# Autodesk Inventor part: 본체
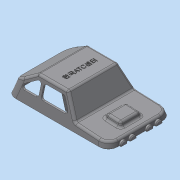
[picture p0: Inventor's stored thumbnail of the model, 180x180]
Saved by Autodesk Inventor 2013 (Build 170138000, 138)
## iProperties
Created: 2015-05
Part Number: 본체
Material: 일반
Document SubType Name: Modeling
Designer: Administrator
Density: 1 g/cm^3
Author: Administrator
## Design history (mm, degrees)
sketch "스케치1"
  geometry: L1 (-61, 38)-(61, 38); L2 (61, 38)-(61, -38); L3 (61, -38)-(-61, -38); L4 (-61, -38)-(-61, 38); L5 (-61, 38)-(61, -38); L6 (61, 38)-(-61, -38); 1 further point
  constraints: 12 end point, 2 midpoint, 2 parallel, 1 horizontal, 1 perpendicular
  dimensions: "d0" = 122 distance of L2.end L3.end; "d2" = 76 distance of L1.end L2.end
extrude "돌출1" new body sketch "스케치1" distance "d3" = 31; taper "d4" = 0 deg
sketch "스케치2"
  geometry: L1 (0, 76)-(0, 0) reference; L2 (0, 76)-(-31, 76) reference; L3 (-31, 0)-(-31, 76) reference; L4 (0, 0)-(-31, 0) reference; L5 (0, 0)-(-31, 8.306); L6 (0, 76)-(-31, 67.694); 1 further point
  constraints: 4 end point, 2 point on line
  dimensions: "d6" = 105 deg angle of L1 L5; "d7" = 105 deg angle of L1 L6
extrude "돌출2" cut sketch "스케치2" stored distance "d8" = 31; taper "d9" = 0 deg
sketch "스케치3"
  geometry: L1 (61, 31)-(-61, 31) reference; L2 (61, 0)-(61, 31) reference; L3 (31, 31)-(57.412, 13.392); L4 (31, 31)-(61, 31); L5 (61, 31)-(61, 11); L6 (61, 0)-(57.412, 13.392); L7 (61, 11)-(61, 0); L8 (57.412, 13.392)-(61, 11); 1 further point
  constraints: 12 end point, 1 collinear, 1 perpendicular, 1 vertical
  dimensions: "d10" = 20 distance of L1.start L5.end; "d12" = 30 distance of L1.start L3.start; "d13" = 15 deg angle of L2 L6; "d14" = 33.6901 deg angle of L1 L3
extrude "돌출3" cut sketch "스케치3" stored distance "d15" = 31; taper "d16" = 0 deg
sketch "스케치4"
  geometry: L1 (-61, 0)-(-59.392, 6); L2 (-61, 0)-(61, 0) reference; L3 (57.412, 13.392)-(61, 0) reference; L4 (61, 0)-(-61, 0) reference; L5 (-61, 0)-(-61, 31) reference; L6 (-61, 31)-(31, 31) reference; L7 (31, 31)-(57.412, 13.392) reference; L8 (-59.392, 6)-(-19, 8.117); L9 (-19, 8.117)-(-4.701, 31); 1 further point
  constraints: 6 end point, 1 point on line
  dimensions: "d17" = 105 deg angle of L2 L1; "d18" = 3 deg angle of L2 L8; "d19" = 6 vertical distance of L1.end L1.start; "d20" = 125 deg angle of L9 L8; "d21" = 42 horizontal distance of L8.end L1.start
extrude "돌출4" cut sketch "스케치4" stored distance "d22" = 31; taper "d23" = 0 deg
sketch "스케치5"
  geometry: L1 (-29.08, 23.392)-(-9.08, 23.392); L2 (-9.08, 23.392)-(-9.08, 49.392); L3 (-9.08, 49.392)-(-29.08, 49.392); L4 (-29.08, 49.392)-(-29.08, 23.392); L5 (-29.08, 23.392)-(-9.08, 49.392); L6 (-9.08, 23.392)-(-29.08, 49.392); L7 (1.92, 74.392)-(1.92, -1.608) reference; 3 further points
  constraints: 12 end point, 3 midpoint, 2 parallel, 1 horizontal, 1 horizontal alignment, 1 perpendicular
  dimensions: "d24" = 26 distance of L1.end L2.end; "d26" = 20 distance of L2.end L3.end; "d27" = 11 distance between parallel lines of L7 L2
extrude "돌출5" join sketch "스케치5" distance "d28" = 5; taper "d29" = -20 deg
fillet "모깎기1" dims "d30" = 12
fillet "모깎기2" dims "d31" = 3
fillet "모깎기3" dims "d32" = 3
feature "쉘1" dims "d33" = 2
sketch "스케치6"
  geometry: L1 (49.27, -35.929)-(-49.27, -35.929) reference; L2 (-58.929, -26.27)-(-58.929, 26.27) reference; L3 (-49.27, 35.929)-(49.27, 35.929) reference; L4 (58.929, 26.27)-(58.929, -26.27) reference; L5 (-59.929, 26.27)-(-59.929, -26.27); L6 (-49.27, -36.929)-(49.27, -36.929); L7 (59.929, -26.27)-(59.929, 26.27); L8 (49.27, 36.929)-(-49.27, 36.929); 5 further points; 4 other entities
  constraints: 8 end point, 7 parallel, 16 other
  dimensions: "d34" = 1 distance between parallel lines of L2 L5
extrude "돌출6" join sketch "스케치6" distance "d35" = 1; taper "d36" = 0 deg
node "작업 평면1"
sketch "스케치7"
  geometry: A1 r 4 centre (-21, 0) between (-17, 0) and (-25, 0); A2 r 4 centre (-10, 0) between (-6, 0) and (-14, 0); A3 r 4 centre (10, 0) between (14, 0) and (6, 0); A4 r 4 centre (21, 0) between (25, 0) and (17, 0); 3 further points
  constraints: 8 point on circle, 4 centre point, 4 horizontal alignment, 9 other
  dimensions: "d38" = 8 diameter of A1; "d39" = 8 diameter of A2; "d40" = 8 diameter of A3; "d41" = 8 diameter of A4; "d42" = 10 distance of point (0, 0) A2.centre; "d43" = 10 distance of A3.centre point (0, 0); "d44" = 11 distance of A4.centre A3.centre; "d45" = 11 distance of A2.centre A1.centre
extrude "돌출7" join sketch "스케치7" stored distance "d46" = 1; taper "d47" = 0 deg
chamfer "모따기1" distance "d48" = 1; stored, may be unused: second distance "d49" = 2, angle "d50" = 45 deg
sketch "스케치8"
  geometry: L1 (-61, -26.409)-(-61, 26.409) reference; 2 further points
  constraints: 1 horizontal alignment, 1 other
  dimensions: "d51" = 50 distance from line of point (-11, 0) L1
feature "엠보싱1" sketch "스케치8" dims "d0" = 122, "d2" = 76, "d52" = 0.5, "d53" = 0
sketch "스케치9"
  geometry: L1 (-3.038, 31)-(13.023, 31) reference; L2 (13.023, 31)-(13.023, 31.5) reference; L3 (13.023, 31.5)-(13.387, 31.5) reference; L4 (13.387, 31.5)-(13.387, 31) reference; L5 (13.387, 31)-(30.092, 31) reference; L6 (31.756, 30.496)-(56.471, 14.02) reference; L7 (57.704, 12.3)-(61, 0) reference; L8 (61, 0)-(59.929, 0) reference; L9 (59.929, 0)-(59.929, -1) reference; L10 (59.929, -1)-(58.929, -1) reference; L11 (58.929, -1)-(58.929, 0) reference; L12 (58.929, 0)-(55.772, 11.782) reference; L13 (55.361, 12.356)-(30.646, 28.832) reference; L14 (30.092, 29)-(-3.038, 29) reference; L15 (-3.886, 28.53)-(-16.476, 8.381) reference; L16 (-20.455, 6.038)-(-28.149, 5.635) reference; L17 (-33.013, 8.674)-(-33.451, 9.705) reference; L18 (-34.424, 10.313)-(-46.566, 9.676) reference; L19 (-47.47, 8.97)-(-47.797, 7.899) reference; L20 (-52.317, 4.368)-(-57.111, 4.117) reference; L21 (-58.025, 3.377)-(-58.929, 0) reference; L22 (-58.929, 0)-(-58.929, -1) reference; L23 (-58.929, -1)-(-59.929, -1) reference; L24 (-59.929, -1)-(-59.929, 0) reference; L25 (-59.929, 0)-(-61, 0) reference; L26 (-61, 0)-(-59.956, 3.895) reference; L27 (-57.216, 6.114)-(-52.422, 6.365) reference; L28 (-49.71, 8.484)-(-49.383, 9.555) reference; L29 (-46.671, 11.674)-(-34.528, 12.31) reference; L30 (-31.61, 10.486)-(-31.172, 9.456) reference; L31 (-28.254, 7.632)-(-20.56, 8.035) reference; L32 (-18.172, 9.441)-(-5.582, 29.59) reference; L33 (19.697, 11)-(-5.89, 11); L34 (-8.435, 15.59)-(-2.811, 24.59); L35 (-0.267, 26)-(19.697, 26); L36 (22.697, 23)-(22.697, 14); L37 (25.578, 23)-(25.578, 14); L38 (43.742, 16.496)-(30.242, 25.496); L39 (42.078, 11)-(28.578, 11); A1 r 3 centre (-3.038, 28) between (-3.038, 31) and (-5.582, 29.59) reference; A2 r 3 centre (30.092, 28) between (31.756, 30.496) and (30.092, 31) reference; A3 r 3 centre (54.806, 11.523) between (57.704, 12.3) and (56.471, 14.02) reference; A4 r 1 centre (54.806, 11.523) between (55.772, 11.782) and (55.361, 12.356) reference; A5 r 1 centre (30.092, 28) between (30.646, 28.832) and (30.092, 29) reference; A6 r 1 centre (-3.038, 28) between (-3.038, 29) and (-3.886, 28.53) reference; A7 r 5 centre (-20.717, 11.031) between (-20.455, 6.038) and (-16.476, 8.381) reference; A8 r 5 centre (-28.411, 10.628) between (-33.013, 8.674) and (-28.149, 5.635) reference; A9 r 1 centre (-34.371, 9.314) between (-33.451, 9.705) and (-34.424, 10.313) reference; A10 r 1 centre (-46.514, 8.678) between (-46.566, 9.676) and (-47.47, 8.97) reference; A11 r 5 centre (-52.579, 9.361) between (-52.317, 4.368) and (-47.797, 7.899) reference; A12 r 1 centre (-57.059, 3.118) between (-57.111, 4.117) and (-58.025, 3.377) reference; A13 r 3 centre (-57.059, 3.118) between (-57.216, 6.114) and (-59.956, 3.895) reference; A14 r 3 centre (-52.579, 9.361) between (-52.422, 6.365) and (-49.71, 8.484) reference; A15 r 3 centre (-46.514, 8.678) between (-46.671, 11.674) and (-49.383, 9.555) reference; A16 r 3 centre (-34.371, 9.314) between (-31.61, 10.486) and (-34.528, 12.31) reference; A17 r 3 centre (-28.411, 10.628) between (-31.172, 9.456) and (-28.254, 7.632) reference; A18 r 3 centre (-20.717, 11.031) between (-20.56, 8.035) and (-18.172, 9.441) reference; A19 r 3 centre (28.578, 23) between (30.242, 25.496) and (25.578, 23); A20 r 3 centre (42.078, 14) between (42.078, 11) and (43.742, 16.496); A21 r 3 centre (19.697, 23) between (22.697, 23) and (19.697, 26); A22 r 3 centre (19.697, 14) between (19.697, 11) and (22.697, 14); A23 r 3 centre (-5.89, 14) between (-8.435, 15.59) and (-5.89, 11); A24 r 3 centre (-0.267, 23) between (-0.267, 26) and (-2.811, 24.59); A25 r 3 centre (28.578, 14) between (25.578, 14) and (28.578, 11); 5 further points
  constraints: 14 end point, 14 point on circle, 14 tangent, 8 point on line, 7 centre point, 5 equal radius, 5 parallel, 1 horizontal alignment, 1 perpendicular
  dimensions: "d54" = 5 distance between parallel lines of L1 L35; "d55" = 5 distance between parallel lines of L32 L34; "d57" = 15 distance of point (22.697, 26) point (22.697, 11); "d62" = 34 distance of point (22.697, 11) point (-11.303, 11); "d63" = 90 deg angle of L33 L36; "d65" = 5 distance between parallel lines of L6 L38; "d68" = 3 radius of A19; "d70" = 15 dimension on A19 L39; "d71" = 3 radius of A25
extrude "돌출8" cut sketch "스케치9" stored distance "d72" = 10; taper "d73" = 0 deg
sketch "스케치10"
  geometry: L1 (-49.409, 38)-(49.409, 38) reference; L2 (49.409, -38)-(-49.409, -38) reference; L3 (59.929, 26.27)-(59.929, -26.27) reference; L4 (61, 6)-(61, -6) reference; L5 (-61, -26.409)-(-61, 26.409) reference; C1 r 3 at (0, -22); C2 r 3 at (0, 22); C3 r 3 at (40, 0); C4 r 3 at (-40, 0); 1 further point
  constraints: 4 centre point, 3 vertical alignment, 2 horizontal alignment
  dimensions: "d74" = 6 diameter of C1; "d75" = 6 diameter of C2; "d76" = 6 diameter of C3; "d77" = 6 diameter of C4; "d78" = 40 distance of point (0, 0) C3.centre; "d79" = 40 distance of C4.centre point (0, 0); "d81" = 22 distance of point (0, 0) C1.centre; "d82" = 22 distance of C2.centre point (0, 0)
extrude "돌출9" join sketch "스케치10" stored distance "d83" = 10; taper "d84" = 2 deg
node "작업 평면2"
sketch "스케치11"
  geometry: L1 (-5, 1)-(5, 1); L2 (5, 1)-(5, -1); L3 (5, -1)-(-5, -1); L4 (-5, -1)-(-5, 1); L5 (-5, 1)-(5, -1); L6 (5, 1)-(-5, -1); L7 (45, -21)-(35, -21); L8 (35, -21)-(35, -23); L9 (35, -23)-(45, -23); L10 (45, -23)-(45, -21); L11 (45, -21)-(35, -23); L12 (35, -21)-(45, -23); L13 (-4.764, -43)-(5.236, -43); L14 (5.236, -43)-(5.236, -45); L15 (5.236, -45)-(-4.764, -45); L16 (-4.764, -45)-(-4.764, -43); L17 (-4.764, -43)-(5.236, -45); L18 (5.236, -43)-(-4.764, -45); L19 (-45, -21)-(-35, -21); L20 (-35, -21)-(-35, -23); L21 (-35, -23)-(-45, -23); L22 (-45, -23)-(-45, -21); L23 (-45, -21)-(-35, -23); L24 (-35, -21)-(-45, -23); C1 r 3 at (0, 0) reference; C2 r 3 at (-40, -22) reference; C3 r 3 at (0, -44) reference; C4 r 3 at (40, -22) reference; A1 r 4.013 centre (0, 0) between (-3.038, -2.621) and (-3.038, 2.621) reference; A2 r 4.013 centre (0, -44) between (-3.038, -46.621) and (-3.038, -41.379) reference; 18 further points; 4 other entities
  constraints: 48 end point, 13 midpoint, 8 parallel, 4 coincident, 4 horizontal, 4 perpendicular, 1 vertical alignment, 8 other
  dimensions: "d86" = 10 distance of L2.end L3.end; "d88" = 2 distance of L1.end L2.end; "d89" = 10 distance of L9.end L8.end; "d90" = 2 distance of L8.end L7.end; "d91" = 10 distance of L14.end L15.end; "d92" = 2 distance of L13.end L14.end; "d93" = 10 distance of L20.end L21.end; "d94" = 2 distance of L19.end L20.end
extrude "돌출10" join sketch "스케치11" stored distance "d95" = 10; taper "d96" = 2.5 deg
sketch "스케치12"
  geometry: L1 (-49.71, 8.484)-(-49.383, 9.555) reference; L2 (-46.671, 11.674)-(-34.528, 12.31) reference; L3 (-31.61, 10.486)-(-31.172, 9.456) reference; L4 (-28.254, 7.632)-(-20.56, 8.035) reference; L5 (-18.172, 9.441)-(-5.582, 29.59) reference; L6 (-3.038, 31)-(13.023, 31) reference; L7 (13.023, 31)-(13.023, 31.5) reference; L8 (13.023, 31.5)-(13.387, 31.5) reference; L9 (13.387, 31.5)-(13.387, 31) reference; L10 (13.387, 31)-(30.092, 31) reference; L11 (31.756, 30.496)-(56.471, 14.02) reference; L12 (57.704, 12.3)-(61, 0) reference; L13 (61, 0)-(59.929, 0) reference; L14 (59.929, 0)-(59.929, -1) reference; L15 (59.929, -1)-(58.929, -1) reference; L16 (58.929, -1)-(58.929, 0) reference; L17 (58.929, 0)-(55.772, 11.782) reference; L18 (55.361, 12.356)-(45.732, 18.775) reference; L19 (45.732, 18.775)-(45, 2) reference; L20 (45, 2)-(43.07, 2) reference; L21 (43.07, 2)-(43, 0) reference; L22 (43, 0)-(37, 0) reference; L23 (37, 0)-(36.93, 2) reference; L24 (36.93, 2)-(35, 2) reference; L25 (35, 2)-(33.924, 26.647) reference; L26 (33.924, 26.647)-(30.646, 28.832) reference; L27 (30.092, 29)-(-3.038, 29) reference; L28 (-3.886, 28.53)-(-16.476, 8.381) reference; L29 (-20.455, 6.038)-(-28.149, 5.635) reference; L30 (-33.013, 8.674)-(-33.451, 9.705) reference; L31 (-34.424, 10.313)-(-34.638, 10.301) reference; L32 (-34.638, 10.301)-(-35, 2) reference; L33 (-35, 2)-(-36.93, 2) reference; L34 (-36.93, 2)-(-37, 0) reference; L35 (-37, 0)-(-43, 0) reference; L36 (-43, 0)-(-43.07, 2) reference; L37 (-43.07, 2)-(-45, 2) reference; L38 (-45, 2)-(-45.338, 9.741) reference; L39 (-45.338, 9.741)-(-46.566, 9.676) reference; L40 (-47.47, 8.97)-(-47.797, 7.899) reference; L41 (-52.317, 4.368)-(-57.111, 4.117) reference; L42 (-58.025, 3.377)-(-58.929, 0) reference; L43 (-58.929, 0)-(-58.929, -1) reference; L44 (-58.929, -1)-(-59.929, -1) reference; L45 (-59.929, -1)-(-59.929, 0) reference; L46 (-59.929, 0)-(-61, 0) reference; L47 (-61, 0)-(-59.956, 3.895) reference; L48 (-57.216, 6.114)-(-52.422, 6.365) reference; L49 (-35, 2)-(-33.598, 9.948); L50 (-40, 0)-(-40, 8.97); L51 (-45, 2)-(-46.355, 9.687); L52 (-46.705, 11.672)-(-46.705, 11.672); A1 r 3 centre (-52.579, 9.361) between (-52.422, 6.365) and (-49.71, 8.484) reference; A2 r 3 centre (-46.514, 8.678) between (-46.671, 11.674) and (-49.383, 9.555) reference; A3 r 3 centre (-34.371, 9.314) between (-31.61, 10.486) and (-34.528, 12.31) reference; A4 r 3 centre (-28.411, 10.628) between (-31.172, 9.456) and (-28.254, 7.632) reference; A5 r 3 centre (-20.717, 11.031) between (-20.56, 8.035) and (-18.172, 9.441) reference; A6 r 3 centre (-3.038, 28) between (-3.038, 31) and (-5.582, 29.59) reference; A7 r 3 centre (30.092, 28) between (31.756, 30.496) and (30.092, 31) reference; A8 r 3 centre (54.806, 11.523) between (57.704, 12.3) and (56.471, 14.02) reference; A9 r 1 centre (54.806, 11.523) between (55.772, 11.782) and (55.361, 12.356) reference; A10 r 1 centre (30.092, 28) between (30.646, 28.832) and (30.092, 29) reference; A11 r 1 centre (-3.038, 28) between (-3.038, 29) and (-3.886, 28.53) reference; A12 r 5 centre (-20.717, 11.031) between (-20.455, 6.038) and (-16.476, 8.381) reference; A13 r 5 centre (-28.411, 10.628) between (-33.013, 8.674) and (-28.149, 5.635) reference; A14 r 1 centre (-34.371, 9.314) between (-33.451, 9.705) and (-34.424, 10.313) reference; A15 r 1 centre (-46.514, 8.678) between (-46.566, 9.676) and (-47.47, 8.97) reference; A16 r 5 centre (-52.579, 9.361) between (-52.317, 4.368) and (-47.797, 7.899) reference; A17 r 1 centre (-57.059, 3.118) between (-57.111, 4.117) and (-58.025, 3.377) reference; A18 r 3 centre (-57.059, 3.118) between (-57.216, 6.114) and (-59.956, 3.895) reference; 1 further point
  constraints: 8 end point, 2 point on circle, 2 point on line, 1 midpoint, 1 perpendicular
  dimensions: "d97" = 10 deg angle of L49 L50; "d99" = 10 deg angle of L50 L51
  node "절단 모서리 투영3"
sketch "스케치13"
  geometry: L1 (61, 4.409)-(61, -48.409) reference; L2 (49.409, -60)-(-49.409, -60) reference; L3 (-61, -48.409)-(-61, -47) reference; L4 (-61, -47)-(-62, -47) reference; L5 (-62, -47)-(-63, -46) reference; L6 (-63, -46)-(-63, -40) reference; L7 (-63, -40)-(-62, -39) reference; L8 (-62, -39)-(-61, -39) reference; L9 (-61, -39)-(-61, -36) reference; L10 (-61, -36)-(-62, -36) reference; L11 (-62, -36)-(-63, -35) reference; L12 (-63, -35)-(-63, -29) reference; L13 (-63, -29)-(-62, -28) reference; L14 (-62, -28)-(-61, -28) reference; L15 (-61, -28)-(-61, -16) reference; L16 (-61, -16)-(-62, -16) reference; L17 (-62, -16)-(-63, -15) reference; L18 (-63, -15)-(-63, -9) reference; L19 (-63, -9)-(-62, -8) reference; L20 (-62, -8)-(-61, -8) reference; L21 (-61, -8)-(-61, -5) reference; L22 (-61, -5)-(-62, -5) reference; L23 (-62, -5)-(-63, -4) reference; L24 (-63, -4)-(-63, 2) reference; L25 (-63, 2)-(-62, 3) reference; L26 (-62, 3)-(-61, 3) reference; L27 (-61, 3)-(-61, 4.409) reference; L28 (-49.409, 16)-(49.409, 16) reference; L29 (-49.27, -57.929)-(49.27, -57.929) reference; L30 (58.929, -48.27)-(58.929, 4.27) reference; L31 (49.27, 13.929)-(-49.27, 13.929) reference; L32 (-58.929, 4.27)-(-58.929, -48.27) reference; L33 (-49.27, 14.929)-(49.27, 14.929) reference; L34 (59.929, 4.27)-(59.929, -48.27) reference; L35 (49.27, -58.929)-(-49.27, -58.929) reference; L36 (-59.929, -48.27)-(-59.929, 4.27) reference; C1 r 3 at (0, 0) reference; C2 r 3 at (-40, -22) reference; C3 r 3 at (40, -22) reference; C4 r 3 at (0, 0) reference; C5 r 3 at (0, -44) reference; 9 further points; 8 other entities
  constraints: 12 other
hole "구멍1" sketch "스케치13" at (0, 0), (0, -44), (40, -22), (-40, -22) diameter "d100" = 3.242; stored, may be unused: countersink angle "d104" = 90 deg, drill point angle "d106" = 118 deg; dims "d101" = 9, "d102" = 4, "d103" = 2, "d105" = 11
feature "면 기울기1" dims angle "d107" = 10 deg
feature "면 기울기2" dims angle "d108" = 10 deg
feature "면 기울기3" dims angle "d109" = 10 deg
feature "면 기울기4" dims angle "d110" = 10 deg
feature "면 기울기5" dims angle "d111" = 10 deg
feature "면 기울기6" dims angle "d112" = 10 deg
feature "면 기울기7" dims angle "d113" = 10 deg
feature "면 기울기8" dims angle "d114" = 10 deg
node "솔리드1"
node "투영된 루프1"
node "투영된 루프2"
node "투영된 루프3"
node "투영된 루프4"
node "절단 모서리 투영1"
node "절단 모서리 투영2"
node "절단 모서리 투영4"
other parameters: "d37" = 63, "d59" = 5, "d85" = -2, "d98" = 10 deg
